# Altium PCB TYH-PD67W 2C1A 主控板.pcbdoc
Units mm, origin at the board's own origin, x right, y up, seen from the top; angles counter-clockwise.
Board outline 94.32 x 66.89 mm, 5 copper layers (Top Layer, Signal Layer 3, Signal Layer 1, Signal Layer 2, Bottom Layer), stack 0.941 mm thick; 54 components, 153 nets, 193 pads, 200 vias.
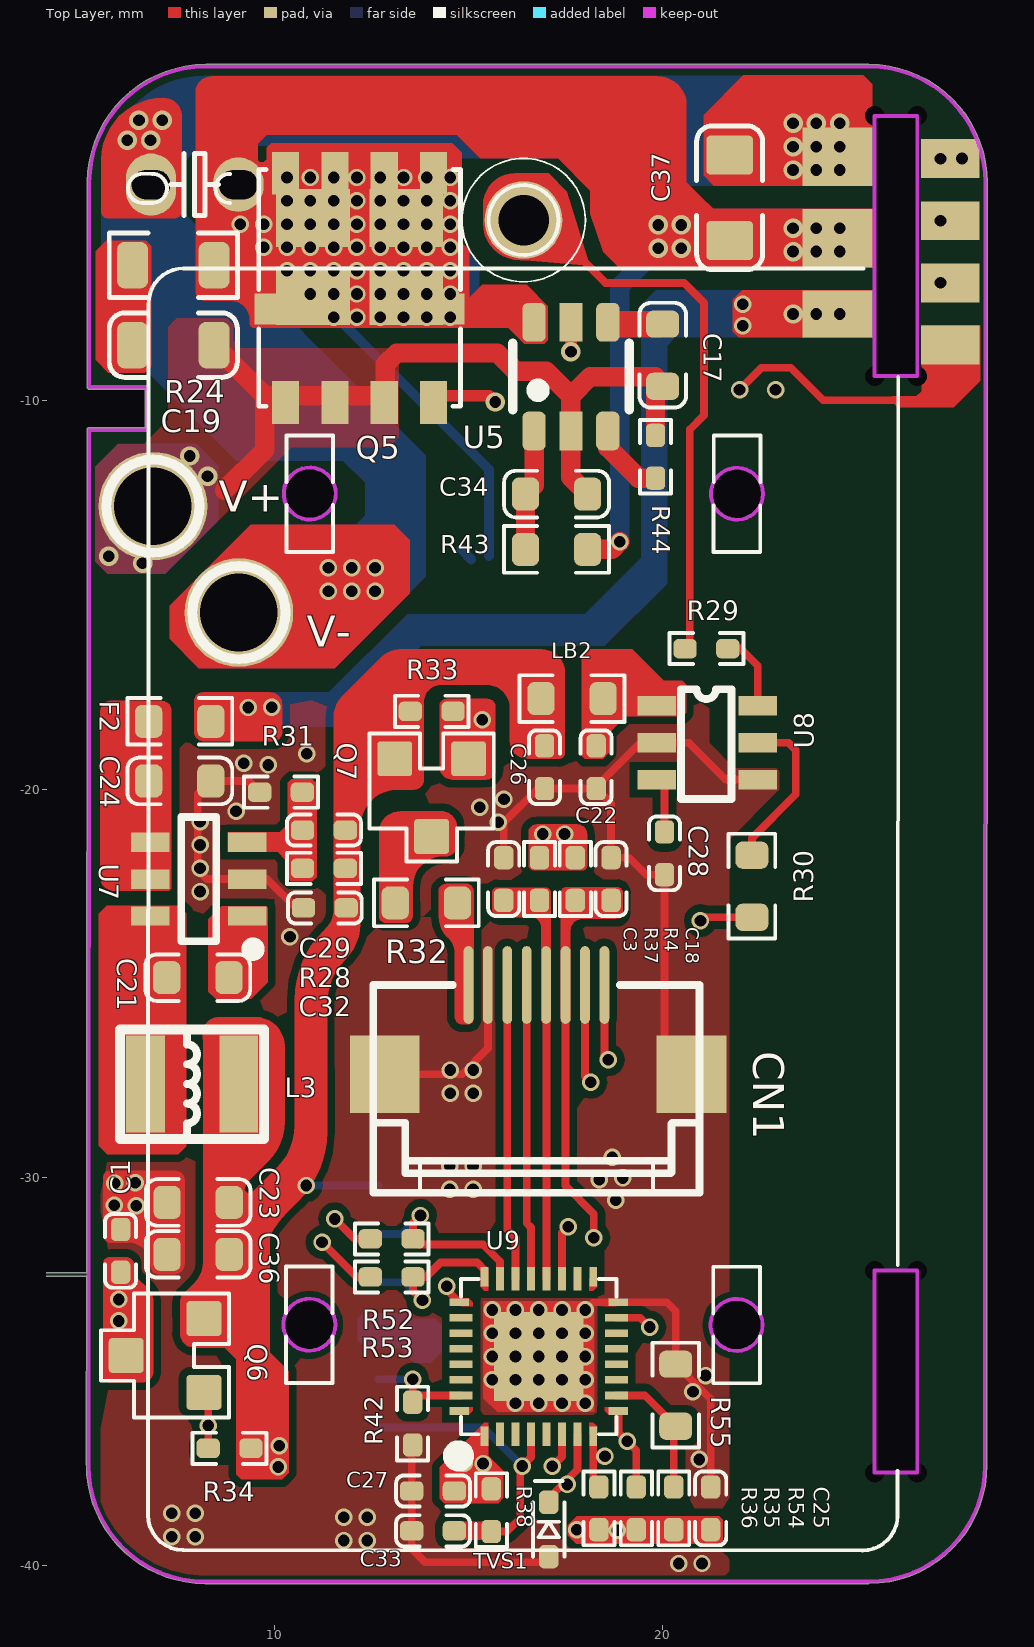
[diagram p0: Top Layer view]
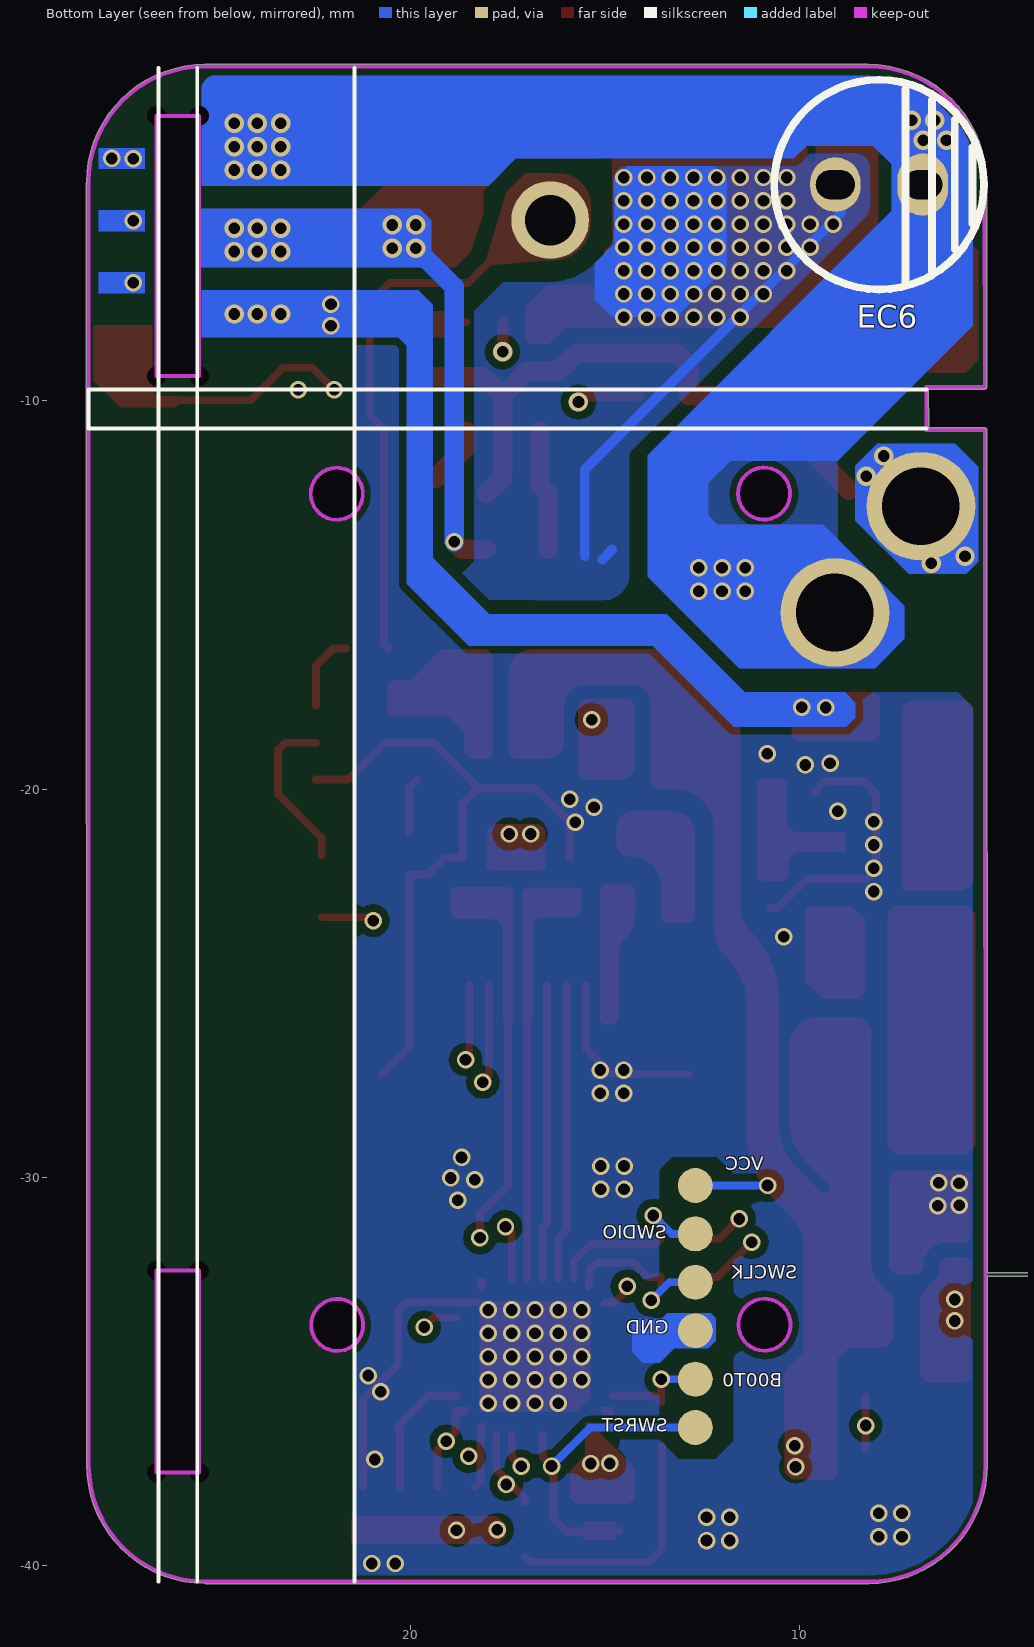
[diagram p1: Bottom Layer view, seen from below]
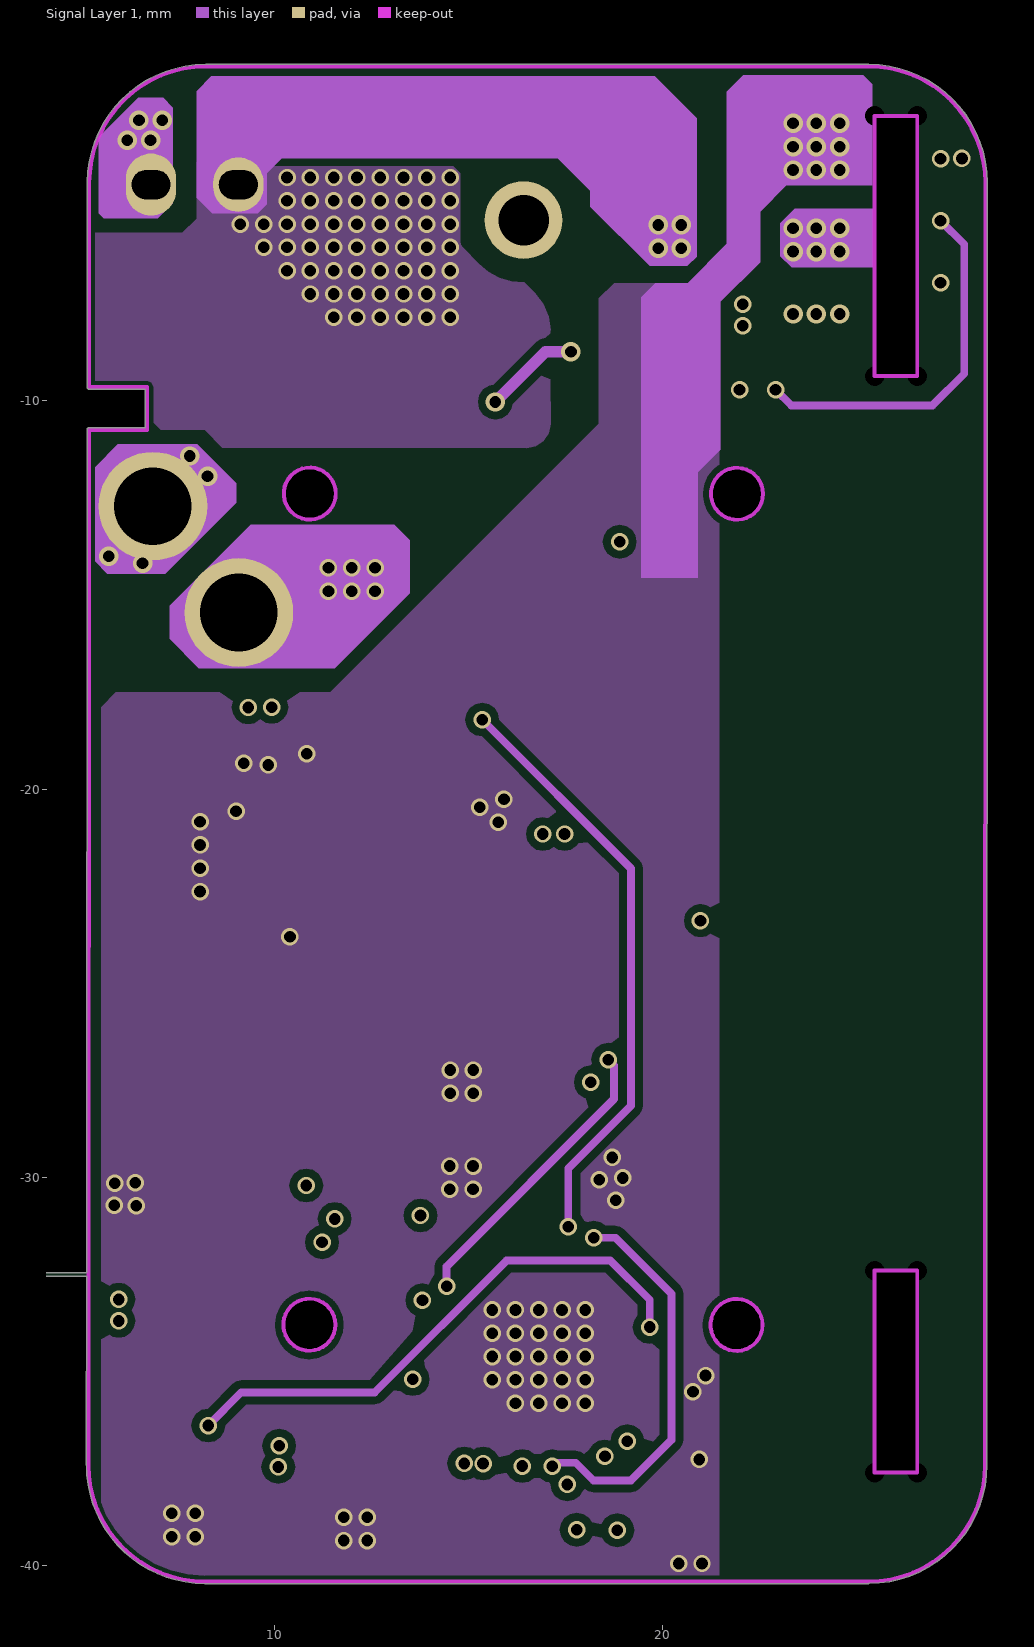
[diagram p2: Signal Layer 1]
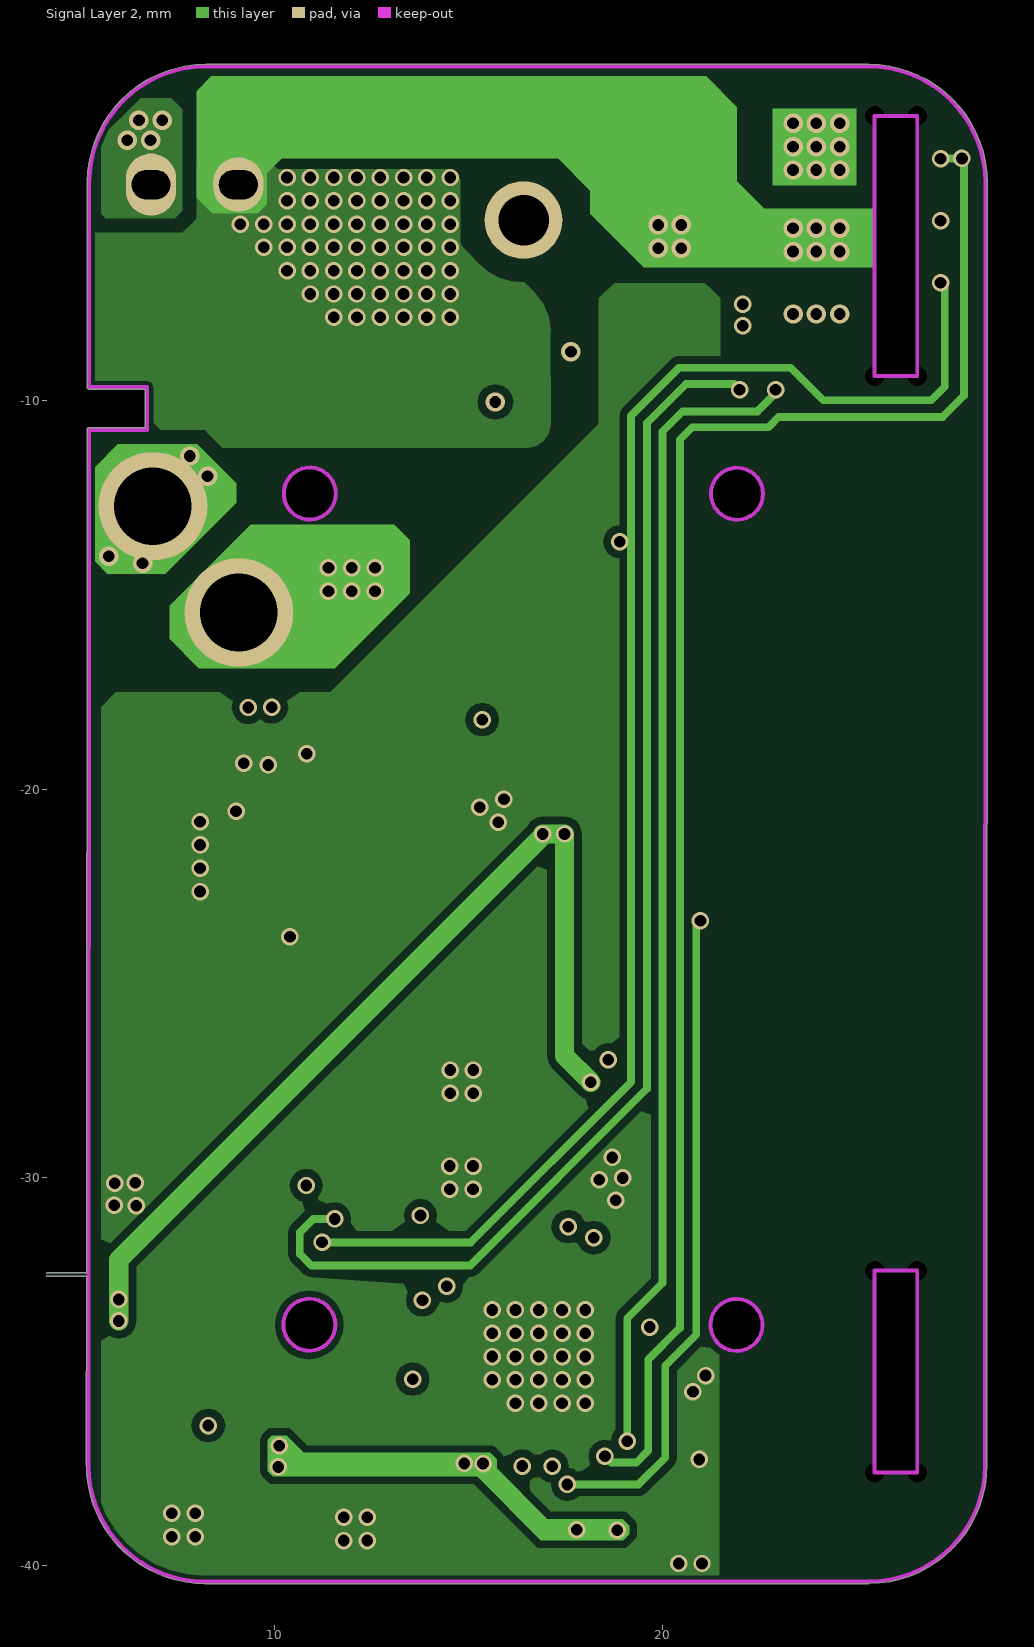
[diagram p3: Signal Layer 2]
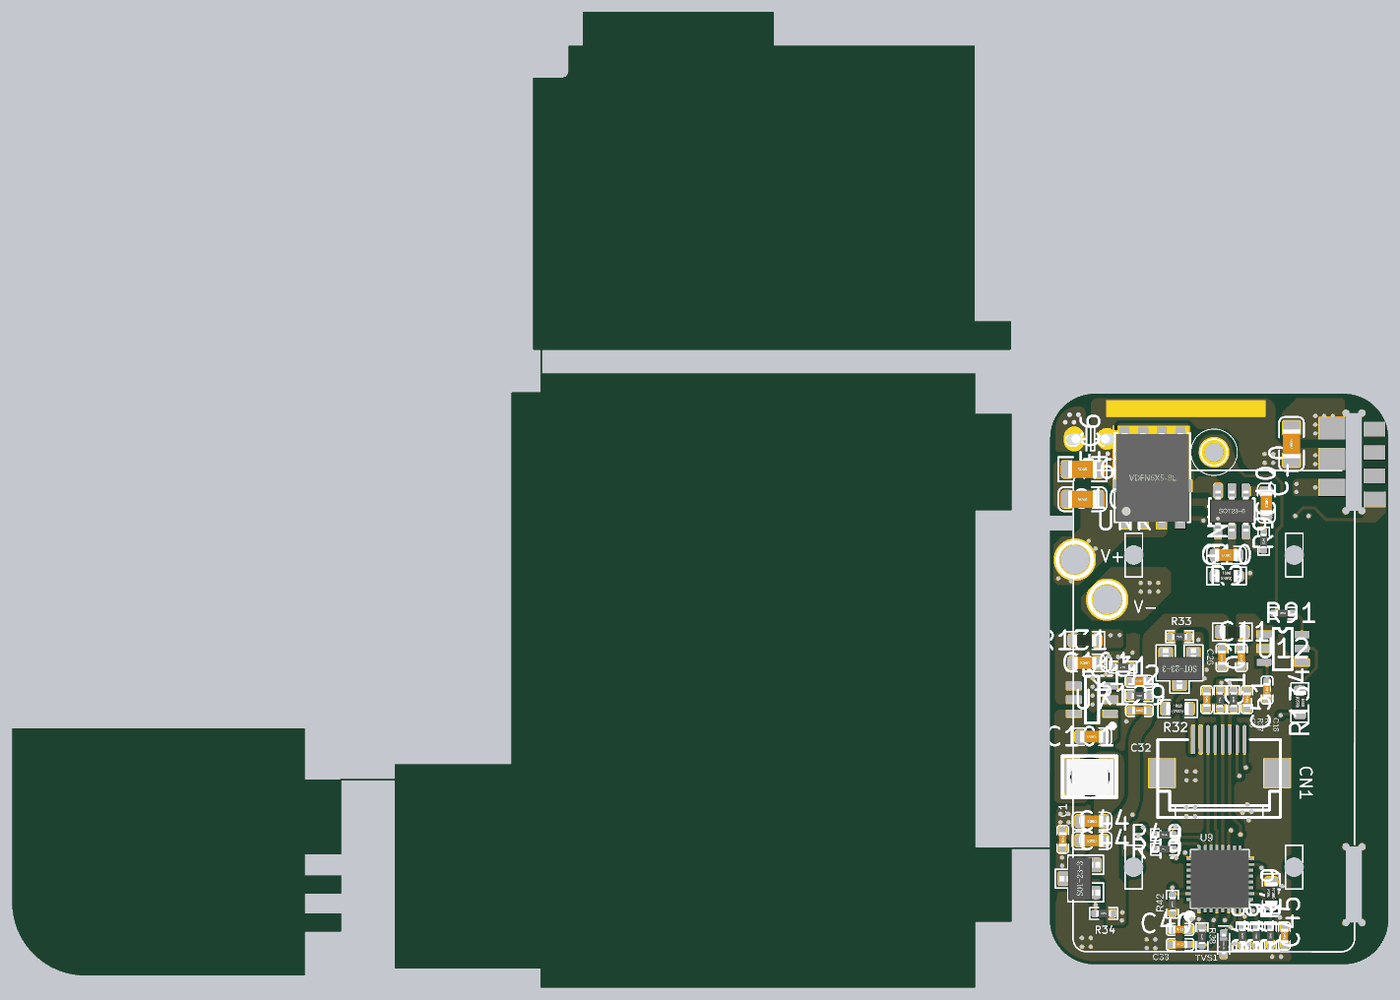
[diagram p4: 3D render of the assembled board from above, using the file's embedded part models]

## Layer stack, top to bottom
Top Solder: solder mask 0.0102, Solder Resist, Dk 3.5
Top Layer: signal copper 0.0356
Dielectric 1: core 0.254, FR-4, Dk 4.2
Signal Layer 3: signal copper 0.036
Dielectric 4: prepreg 0.127, Dk 4.2
Signal Layer 1: signal copper 0.036
Dielectric 2: core 0.254, Dk 4.2
Signal Layer 2: signal copper 0.036
Dielectric 3: prepreg 0.127, Dk 4.2
Bottom Layer: signal copper 0.0356
Bottom Solder: solder mask 0.0102, Solder Resist, Dk 3.5

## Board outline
-60.945,-41.225 -45.944,-41.225 ccw(c-45.944,-41.2) -45.919,-41.2 -45.919,-38.225 -43.445,-38.225 ccw(c-43.445,-38.2) -43.419,-38.2 -43.419,-37 ccw(c-43.445,-37) -43.445,-36.975 -45.919,-36.975 -45.919,-35.625 -43.445,-35.625 ccw(c-43.445,-35.6) -43.419,-35.6 -43.419,-34.4 ccw(c-43.445,-34.4) -43.445,-34.375 -45.919,-34.375 -45.919,-32.925 -43.445,-32.925 ccw(c-43.445,-32.9) -43.419,-32.9 -43.419,-27.85 -39.751,-27.85 -39.759,-40.693 ccw(c-39.709,-40.7) -39.709,-40.75 -29.759,-40.752 -29.76,-42.002 ccw(c-29.71,-42.002) -29.71,-42.052 0,-42.052 ccw(c0,-42.002) 0.05,-42.002 0.05,-37.55 2.5,-37.55 ccw(c2.5,-37.5) 2.55,-37.5 2.55,-32.55 5.163,-32.55 5.16,-37.409 ccw(c5.21,-37.409) 5.16,-37.409 ccw(c8.207,-37.409) 8.207,-40.456 ccw(c8.207,-40.406) 8.207,-40.456 ccw(c8.207,-40.406) 8.207,-40.456 25.296,-40.456 ccw(c25.296,-40.406) 25.308,-40.455 ccw(c25.296,-37.407) 28.344,-37.407 28.352,-4.393 ccw(c28.302,-4.393) 28.352,-4.393 ccw(c28.302,-4.393) 28.351,-4.381 ccw(c25.304,-4.393) 25.304,-1.346 8.229,-1.346 ccw(c8.229,-4.393) 5.181,-4.375 ccw(c5.228,-4.393) 5.178,-4.393 5.175,-9.653 ccw(c5.225,-9.653) 5.225,-9.703 6.674,-9.704 6.673,-10.703 5.225,-10.702 ccw(c5.225,-10.753) 5.174,-10.753 5.163,-32.45 0.05,-32.45 0.05,-9.32 2.5,-9.32 ccw(c2.5,-9.269) 2.55,-9.269 2.55,-2.769 ccw(c2.5,-2.769) 2.5,-2.719 0.05,-2.719 0.05,0 ccw(c0,0) 0,0.05 -29.65,0.05 -29.65,1.682 2.433,1.682 ccw(c2.433,1.733) 2.483,1.733 ccw(c2.433,1.733) 2.482,1.745 ccw(c2.45,1.784) 2.5,1.784 2.5,3.584 ccw(c2.45,3.584) 2.45,3.635 0,3.635 0,22.484 ccw(c-0.05,22.484) -0.014,22.52 ccw(c-0.05,22.484) -0.05,22.535 -13.768,22.535 -13.768,24.784 ccw(c-13.819,24.784) -13.819,24.835 -26.819,24.835 ccw(c-26.819,24.784) -26.869,24.784 -26.869,22.535 -27.789,22.535 ccw(c-27.789,22.484) -27.84,22.483 -27.84,20.784 cw(c-28.289,20.784) -28.289,20.335 cw(c-28.289,20.784) -28.289,20.335 cw(c-28.289,20.284) -28.289,20.335 -30.217,20.335 ccw(c-30.217,20.284) -30.268,20.284 -30.268,1.733 ccw(c-30.217,1.733) -30.217,1.682 -29.75,1.682 -29.75,-1.25 -31.7,-1.25 ccw(c-31.7,-1.3) -31.75,-1.3 -31.75,-26.75 -39.7,-26.75 ccw(c-39.7,-26.8) -39.75,-26.8 -39.751,-27.75 -43.445,-27.75 ccw(c-43.445,-27.8) -43.488,-27.775 -45.919,-27.775 -45.919,-24.3 ccw(c-45.945,-24.3) -45.945,-24.275 -65.945,-24.275 ccw(c-65.945,-24.3) -65.97,-24.3 -65.97,-36.2 ccw(c-60.945,-36.2)
cut-out: 26.55,-32.4 25.45,-32.4 25.45,-37.6 26.55,-37.6
cut-out: 25.45,-9.369 26.55,-9.369 26.55,-2.669 25.45,-2.669
cut-out: 11.579,-12.393 11.579,-12.392 ccw(c10.912,-12.392) 10.912,-11.725 10.902,-11.725 ccw(c10.902,-12.39) 10.237,-12.39 10.237,-12.418 ccw(c10.889,-12.418) 10.889,-13.07 10.902,-13.07 ccw(c10.902,-12.393)
cut-out: 11.567,-33.793 11.567,-33.792 ccw(c10.9,-33.792) 10.9,-33.125 10.89,-33.125 ccw(c10.89,-33.79) 10.226,-33.79 10.226,-33.818 ccw(c10.877,-33.818) 10.877,-34.47 10.89,-34.47 ccw(c10.89,-33.793)
cut-out: 22.567,-33.799 22.567,-33.798 ccw(c21.9,-33.798) 21.9,-33.131 21.89,-33.131 ccw(c21.89,-33.796) 21.226,-33.796 21.226,-33.824 ccw(c21.877,-33.824) 21.877,-34.476 21.89,-34.476 ccw(c21.89,-33.799)
cut-out: 22.579,-12.399 22.579,-12.398 ccw(c21.912,-12.398) 21.912,-11.731 21.902,-11.731 ccw(c21.902,-12.396) 21.237,-12.396 21.237,-12.424 ccw(c21.889,-12.424) 21.889,-13.076 21.902,-13.076 ccw(c21.902,-12.399)

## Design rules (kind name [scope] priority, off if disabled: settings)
Clearance Clearance_19 [InNet('NetC4_2') vs InNet('PGND')] p1: gap=0.4
Clearance Clearance_18 [InNet('NetR15_1') vs InNet('PGND')] p2: gap=1
Clearance Clearance_17 [InNet('NetN_1') vs InNet('NetBD1_1')] p3: gap=1.55
Clearance Clearance_16 [InNet('NetN_1') vs InNet('PGND')] p4: gap=1.5
Clearance Clearance_15 [InNet('VIN') vs InNet('PGND')] p5 off: gap=5.8
Clearance Clearance_14 [InNet('CS') vs InNet('Bais-L')] p6: gap=0.45
Clearance Clearance_13 [InNet('SW') vs InNet('CS')] p7: gap=1.5
Clearance Clearance_12 [InNet('NetR15_1') vs InNet('CS')] p8: gap=1
Clearance Clearance_11 [InNet('NetBD1_3') vs InNet('CS')] p9: gap=1.1
Clearance Clearance_10 [InNet('HV') vs InNet('CS')] p10: gap=1.1
Clearance Clearance_9 [InNet('NetL2_1') vs InNet('CS')] p11: gap=1.5
Clearance Clearance_8 [InNet('NetC1_2') vs InNet('PGND')] p12: gap=1.2
Clearance Clearance_7 [InNet('NetBD1_3') vs InNet('PGND')] p13: gap=1.2
Clearance Clearance_6 [InNet('NetC2_2') vs InNet('PGND')] p14: gap=1.3
Clearance Clearance_5 [InNet('Bais-L') vs InNet('PGND')] p15: gap=0.45
Clearance Clearance_4 [InNet('SW') vs InNet('PGND')] p16: gap=1.5
Clearance Clearance_3 [InNet('HV') vs InNet('PGND')] p17: gap=1.2
Clearance Clearance_2 [InNet('NetL2_1') vs InNet('PGND')] p18: gap=1.5
Clearance Clearance_1 [OnLayer('Keep-Out Layer')] p19: gap=0.1
Clearance [All] p20: gap=0.2
PlaneConnect [All] p1: planeconnectstyle=Direct reliefexpansion=0.508 reliefentries=4 reliefconductorwidth=0.3 reliefairgap=0.254
PolygonConnect [All] p1: connectstyle=Direct reliefconductorwidth=0.3 reliefentries=4 polygonreliefangle="90 Angle" airgapwidth=0.3
RoutingVias [All] p1: holewidth=0.711 width=1.27 viastyle="Through Hole" minholewidth=0.711 minwidth=1.27 maxholewidth=0.711 maxwidth=1.27
SolderMaskExpansion [All] p1: expansion=0.05
Width [All] p1: maxlimit=10 minlimit=0.1 preferedwidth=0.2
28 further rules are at their usual default settings.

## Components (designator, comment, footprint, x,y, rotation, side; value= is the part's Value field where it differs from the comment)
C1 "100nF 0402" 0402C 6.439,-30.942 r270 top
C3 "NC/0402" 0402C 16.302,-21.368 r270 top
C17 "2.2nF/250V/0805" 0603CX#1 19.995,-8.031 r270 top (schematic designator C10)
C18 "NC/0402" 0402C 19.066,-21.368 r270 top (schematic designator C2)
C19 "2.2nF/250V/0805" 0805CX 8.445,-8.572 r180 top (schematic designator C10)
C21 "104/50V X7R 0603" 0603CX#1 7.226,-24.856 r0 top (schematic designator C101)
C22 "106/10V" 0402C 17.882,-20.389 r90 top (schematic designator C101)
C23 "10uF/10V" 0603CX#1 8.836,-30.645 r180 top (schematic designator C44)
C24 "104/50V X7R 0603" 0603CX#1 8.361,-19.794 r180 top (schematic designator C101)
C25 "1uF/25V" 0402C 21.631,-37.57 r270 top (schematic designator C45)
C26 "10nF" 0402C 16.553,-20.389 r90 top (schematic designator C4)
C27 "0.1uF/25V" 0402C 13.132,-37.674 r0 top (schematic designator C40)
C28 "104/25V/NC" 0402C 19.642,-22.606 r90 top (schematic designator C51)
C29 "NC" 0402C 10.323,-20.658 r0 top (schematic designator C112)
C32 "1uF" 0402C 10.347,-22.661 r0 top (schematic designator C5)
C33 "100nF" 0402C 13.132,-38.7 r0 top (schematic designator C6)
C34 "2.2nF/250V/0805" 0603CX#2 17.262,-12.406 r180 top (schematic designator C10)
C36 "10uF/10V" 0603CX#1 8.836,-31.982 r180 top (schematic designator C44)
C37 "2.2nF/250V/0805" 0805C 20.869,-6.628 r90 top (schematic designator C10)
CN1 "8.07A0.006200" "70W 屏座" 16.693,-25.17 r270 top locked
EC6 "560uF/25V/6.3*16" EG-5*17L 7.946,-4.438 r90 bottom
F2 "10KF 0402" 0603LX 6.761,-18.259 r0 top (schematic designator R131)
L3 "3.3uH NR3010" NR3010 7.885,-27.593 r0 top (schematic designator L4)
LB2 "104/25V" 0603LX 18.462,-17.671 r180 top (schematic designator C11)
Q5 "Comment" DFN5*6 10.286,-10.048 r0 top
Q6 "2N7002KL SOT-23" SOT-23_R 7.183,-34.585 r90 top (schematic designator Q8)
Q7 "2N7002KL SOT-23" SOT-23_R 14.047,-20.221 r180 top (schematic designator Q8)
R4 "4.7K" 0402R 17.745,-21.768 r270 top
R24 "10R/1206" 0805RX 8.445,-6.513 r180 top (schematic designator R6)
R28 "31.6KF 0402" 0402R 10.723,-22.042 r0 top (schematic designator R129)
R29 "10K" 0402R 21.672,-16.386 r180 top (schematic designator R91)
R30 "100R" 0603RX#1 22.293,-22.503 r270 top (schematic designator R134)
R31 "10KF 0402" 0402R 9.618,-20.082 r0 top (schematic designator R131)
R32 "10R" 0603RX#2 13.11,-22.934 r0 top (schematic designator R2)
R33 "10K" 0402R 13.498,-18 r0 top (schematic designator R1)
R34 "10K" 0402R 9.393,-36.975 r180 top (schematic designator R3)
R35 "4K7 NC" 0402R 19.316,-37.97 r270 top (schematic designator R49)
R36 "4K7 NC" 0402R 18.353,-37.97 r270 top (schematic designator R49)
R37 "4.7K" 0402R 16.823,-21.768 r270 top (schematic designator R5)
R38 "10K" 0402R 15.583,-39.117 r90 top (schematic designator R6)
R42 "10K" 0402R 13.558,-36.889 r90 top (schematic designator R7)
R43 "51R/0402" 0603RX#1 17.263,-13.831 r0 top (schematic designator R9)
R44 "51R/0402" 0402R 19.81,-10.896 r270 top (schematic designator R9)
R52 "4K7 NC" 0402R 12.468,-31.582 r0 top (schematic designator R49)
R53 "4K7 NC" 0402R 12.468,-32.563 r0 top (schematic designator R49)
R54 "4K7 NC" 0402R 20.28,-37.97 r270 top (schematic designator R49)
R55 "4K7 NC" 0603rx 20.33,-35.608 r90 top (schematic designator R49)
TVS1 "Comment" SOD-723 17.062,-39.065 r90 top
U5 "Comment" SOT-23-6S 16.683,-10.783 r90 top
U7 "RY9420BT6" SOT-23-6#1 8.051,-22.32 r180 top
U8 "RM1233A" SOT-23-6#2 21.143,-18.808 r0 top (schematic designator U12)
U9 "Comment" "QFN4*4-32L TYH" 16.805,-34.612 r0 top
V+ "Comment" PAD-AC 6.869,-12.718 r0 top
V- "Comment" PAD-AC 9.083,-15.458 r0 top

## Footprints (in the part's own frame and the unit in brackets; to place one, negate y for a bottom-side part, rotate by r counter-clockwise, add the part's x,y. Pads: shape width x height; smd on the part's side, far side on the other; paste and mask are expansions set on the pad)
"70W 屏座" [mm]
  oval 2x0.25 smd: 1(-0.124,-1.698) 2(-0.124,-1.198) 3(-0.124,-0.698) 4(-0.124,-0.198) 5(-0.124,0.302) 6(-0.124,0.802) 7(-0.124,1.302) 8(-0.124,1.802)
  rect 2x1.8 smd: 2(2.176,-3.855) 2(2.176,4.045)
  silkscreen extent -0.12,-4.15 5.23,4.25
0402C [mm]
  rrect50% 0.6x0.5 smd: 1(0.4,-0.4) 2(1.5,-0.4)
  silkscreen extent 0,-0.8 1.9,0, body extent 0.45,-0.66 1.45,-0.14, height 0.53
0402R [mm]
  rrect50% 0.6x0.5 smd: 1(0,0) 2(1.1,0)
  silkscreen extent -0.4,-0.4 1.5,0.4, body extent 0.05,-0.25 1.05,0.25, height 0.3
0603CX#1 [mm]
  rrect50% 0.7x0.85 smd: 1(0,0) 2(1.6,0)
  silkscreen extent -0.55,-0.6 2.15,0.6, body extent 0,-0.41 1.6,0.41, height 0.81
0603CX#2 [mm]
  rrect50% 0.7x0.85 smd: 1(-0.8,0) 2(0.8,0)
  silkscreen extent -1.35,-0.6 1.35,0.6, body extent -0.8,-0.41 0.8,0.41, height 0.81
0603LX [mm]
  rrect50% 0.7x0.85 smd: 1(0,0) 2(1.6,0)
  silkscreen extent -0.55,-0.6 2.15,0.6, body extent -0.02,-0.4 1.58,0.4, height 0.4
0603RX#1 [mm]
  rrect50% 0.7x0.85 smd: 1(-0.8,0) 2(0.8,0)
  silkscreen extent -1.35,-0.6 1.35,0.6, body extent -0.77,-0.42 0.78,0.43, height 0.45
0603RX#2 [mm]
  rrect50% 0.7x0.85 smd: 1(0,0) 2(1.6,0)
  silkscreen extent -0.55,-0.6 2.15,0.6, body extent 0.03,-0.42 1.58,0.43, height 0.45
0603rx [mm]
  rrect50% 0.7x0.85 smd: 1(-0.8,0) 2(0.8,0)
  silkscreen extent -1.35,-0.6 1.35,0.6, body extent -0.77,-0.42 0.78,0.43, height 0.45
0805C [mm]
  rrect20% 1x1.2 smd: 1(0.75,-0.85) 2(2.95,-0.85)
  silkscreen extent 0,-1.7 3.7,0, body extent 0.85,-1.46 2.85,-0.24, height 0.51
0805CX [mm]
  rrect50% 0.8x1.2 smd: 1(0,0) 2(2.1,0)
  silkscreen extent -0.6,-0.83 2.7,0.83, body extent 0.05,-0.61 2.05,0.61, height 0.51
0805RX [mm]
  rrect50% 0.8x1.2 smd: 1(0,0) 2(2.1,0)
  silkscreen extent -0.6,-0.83 2.7,0.83, body extent 0.05,-0.61 2.05,0.61, height 0.51
DFN5*6 [mm]
  rect 0.7x1.1 smd: 1(0,0) 2(1.27,0) 3(2.54,0) 4(3.81,0) 5(3.81,5.9) 6(2.54,5.9) 7(1.27,5.9) 8(0,5.9)
  rect 1x0.8 smd: 8(-0.295,2.402) 8(4.105,2.402)
  rect 1.9x1.5 smd: 8(0.705,2.75) 8(0.705,4.75) 8(3.105,2.75) 8(3.105,4.75)
  silkscreen extent -0.69,-0.1 4.51,6, body extent -0.59,-0.1 4.41,6, height 1.06
EG-5*17L [mm]
  oval 1.4x1.3 hole 0.75 slot 1 at 90 deg: 1(0,1.125)
  oval 1.6x1.3 hole 0.75 slot 1 at 90 deg: 2(0,-1.125)
  silkscreen extent -2.7,-2.7 2.7,2.7, body extent -2.7,-2.7 2.7,2.7, height 17
NR3010 [mm]
  rect 1x2.5 smd: 1(-1.206,-0.001) 2(1.194,-0.001)
  silkscreen extent -1.87,-1.42 1.84,1.4, body extent -1.58,-1.38 1.63,1.34, height 2
PAD-AC [mm]
  round 2.8 hole 2: 1(0,0)
  silkscreen extent -1.2,-1.2 1.2,1.2
"QFN4*4-32L TYH" [mm]
  rect 0.2x0.5 smd: 1(-1.4,-2.05) 8(1.4,-2.05) 17(1.4,2.05) 24(-1.4,2.05)
  rect 0.2x0.6 smd: 2(-1,-2) 3(-0.6,-2) 4(-0.2,-2) 5(0.2,-2) 6(0.6,-2) 7(1,-2) 18(1,2) 19(0.6,2) 20(0.2,2) 21(-0.2,2) 22(-0.6,2) 23(-1,2)
  rect 0.5x0.2 smd: 9(2.05,-1.4) 16(2.05,1.4) 25(-2.05,1.4) 32(-2.05,-1.4)
  rect 0.6x0.2 smd: 10(2,-1) 11(2,-0.6) 12(2,-0.2) 13(2,0.2) 14(2,0.6) 15(2,1) 26(-2,1) 27(-2,0.6) 28(-2,0.2) 29(-2,-0.2) 30(-2,-0.6) 31(-2,-1)
  rect 2.3x2.3 smd: 33(0,0)
  Top Layer region: -1.425,1.425 1.425,1.425 1.425,-1.425 -1.075,-1.425 -1.425,-1.075
  Top Layer region: -2,-1.5 -1.8,-1.5 -1.7,-1.4 -1.7,-1.3 -2,-1.3
  Top Layer region: -2,1.5 -1.8,1.5 -1.7,1.4 -1.7,1.3 -2,1.3
  Top Layer region: 1.5,-2 1.5,-1.8 1.4,-1.7 1.3,-1.7 1.3,-2
  Top Layer region: -1.5,-2 -1.5,-1.8 -1.4,-1.7 -1.3,-1.7 -1.3,-2
  Top Layer region: 2,-1.5 1.8,-1.5 1.7,-1.4 1.7,-1.3 2,-1.3
  Top Layer region: 2,1.5 1.8,1.5 1.7,1.4 1.7,1.3 2,1.3
  Top Layer region: 1.5,2 1.5,1.8 1.4,1.7 1.3,1.7 1.3,2
  Top Layer region: -1.5,2 -1.5,1.8 -1.4,1.7 -1.3,1.7 -1.3,2
  silkscreen extent -2.27,-2.76 2,2, body extent -2,-2 2,2, height 0.75
SOD-723 [mm]
  rrect50% 0.6x0.5 smd: 1(-0.7,0) 2(0.7,0)
  silkscreen extent -0.7,-0.41 1.25,0.41, body extent -0.7,-0.3 0.7,0.3, height 0.53
SOT-23-6#1 [mm]
  rect 1x0.5 smd: 1(-1.25,0.95) 2(-1.25,0) 3(-1.25,-0.95) 4(1.25,-0.95) 5(1.25,0) 6(1.25,0.95)
  silkscreen extent -1.5,-1.6 0.45,1.9, body extent -1.4,-1.5 1.4,1.5, height 1.15
SOT-23-6#2 [mm]
  rect 1x0.5 smd: 1(-1.3,0.95) 2(-1.3,0) 3(-1.3,-0.95) 4(1.3,-0.95) 5(1.3,0) 6(1.3,0.95)
  silkscreen extent -0.67,-1.45 0.63,1.37
SOT-23-6S [mm]
  rrect50% 1x0.6 smd: 1(0,0) 3(0,-1.9) 4(2.8,-1.9) 6(2.8,0)
  rect 1x0.6 smd: 2(0,-0.95) 5(2.8,-0.95)
  silkscreen extent 0.55,-2.45 2.25,0.55, body extent -0.01,-2.45 2.8,0.55, height 1.15
SOT-23_R [mm]
  rrect20% 0.9x0.9 smd: 1(-0.95,-1) 2(0.95,-1) 3(0,1)
  silkscreen extent -1.6,-1.65 1.6,1.65, body extent -1.46,-1.44 1.44,1.36, height 1.2

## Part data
C1 C3 C18 C26 C32 C33: library part CAP_0603
C17 C19 C34 C37: library part CAP
C23 C25 C27 C36: library part CAP, "X7R, 25V, +/-5%"
C29: library part "CAP SEMI"
EC6: library part CAPACITOR, "C?"
L3: library part Inductor, "102125 铁?"
LB2: library part CAPZ
Q6 Q7: library part NMOS
R4 R32 R33 R34 R37 R38 R42: library part Res_0603
R24 R43 R44: library part Res1, "Resistor"
R35 R36 R52 R53 R54 R55: library part RES2Z
U7: library part ME3121, "DC-DC BUCK"
U8: "U?"

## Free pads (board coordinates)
  round 0.9 smd far side: 0(12.678,-36.441) 0(12.678,-35.195) 0(12.678,-33.948) 0(12.678,-32.702) 0(12.678,-31.455) 0(12.678,-30.209)
  round 2 hole 1.3: 0(16.412,-5.352)
  rect 1.8x1.2 smd: 3(24.5,-7.769)
  rect 1.8x1.5 smd: 3(24.5,-5.819) 3(24.5,-3.719)
  rect 1.5x1 smd: 3(27.4,-8.569) 3(27.4,-6.969) 3(27.4,-5.369) 3(27.4,-3.769)
  round 0.2 hole 0.5: 8(26.55,-9.369) 9(25.45,-9.369) 10(25.45,-2.669) 11(26.55,-2.669) 12(25.45,-32.4) 13(26.55,-32.4) 14(25.45,-37.6) 15(26.55,-37.6)

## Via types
v1: diameter 0.45, hole 0.3, Top Layer to Bottom Layer, tented both sides, 168 vias
v2: diameter 0.5, hole 0.3, Top Layer to Bottom Layer, tented both sides, 32 vias

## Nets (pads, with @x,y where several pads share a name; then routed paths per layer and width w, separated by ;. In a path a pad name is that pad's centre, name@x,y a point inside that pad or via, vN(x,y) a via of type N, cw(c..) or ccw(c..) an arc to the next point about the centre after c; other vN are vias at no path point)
3.3V: C22.2 LB2.1 U8.1 | length 2.8
  Top Layer w0.2: C22.2 18.282,-17.851 LB2.1 18.65,-17.858 U8.1
A: 
A+: 
A-: 
Bais-L: 
BOOT0: pad.0@12.678,-35.195 R42.2 U9.31 | length 2.8
  Top Layer w0.2: v1(13.558,-35.195) R42.2 13.734,-35.612 U9.31
  Bottom Layer w0.2: pad.0@12.678,-35.195 v1(13.558,-35.195)
CC1: 
CC2: 
CPA: 
CS: CN1.8 U9.25 | length 10.3
  Top Layer w0.2: v1(14.432,-32.803) 14.432,-32.89 U9.25 ; CN1.8 18.495,-26.871 v1(18.592,-26.969)
  Signal Layer 1 w0.2: v1@14.534,-32.803 v1(14.432,-32.803) 14.432,-32.293 18.743,-27.983 18.743,-27.119 v1(18.592,-26.969)
D: 
D+: 
D-: 
DM: 
DP: 
EM: 
EN: 
EN_IC: 
FB: 
G-SR: Q5.4 U5.5 | length 4.9
  Top Layer w0.3: Q5.4@14.119,-9.878 15.529,-9.878 v2(15.686,-10.035) ; v2(17.633,-8.744) U5.5
  Signal Layer 1 w0.3: v2(15.686,-10.035) 16.977,-8.744 v2(17.633,-8.744)
GND-C: 
HV: 
ISET: 
KEY: R30.2 TVS1.2 U9.7 | length 20.4
  Top Layer w0.2: TVS1.2 17.062,-38.258 17.805,-37.516 U9.7 ; v1(20.969,-23.388) 21.053,-23.303 R30.2
  Signal Layer 2 w0.2: v1(17.542,-37.905) 19.374,-37.905 20.06,-37.219 20.06,-34.848 20.859,-34.048 20.859,-23.497 v1(20.969,-23.388)
KEY1: R29.1 U8.6 | length 2
  Top Layer w0.2: R29.1 22.004,-16.386 22.443,-16.825 U8.6
LEDA: CN1.1 R32.2
M: 
N: 
NetBD1_1: 
NetBD1_3: 
NetBD2_1: 
NetC1_2: 
NetC2_2: 
NetC3_2: 
NetC4_1: 
NetC4_2: 
NetC6_1: 
NetC10_2: C19.2 R24.2 | length 2.1
  Top Layer w0.254: C19.2@6.306,-8.553 R24.2@6.306,-6.494
NetC21_1: 
NetC22_1: 
NetC24_1: C24.2 F2.1 U7.4 U7.5
NetC25_2: 
NetC26_2: 
NetC30_2: 
NetC31_2: 
NetC100_2: 
NetC101_1: C21.1 L3.1 U7.6
NetC101_2: C21.2 U7.1
NetC112_1: C29.1 R28.1 R31.2 U7.3
NetD4_K: 
NetF1_1: 
NetF1_2: 
NetKEY1_1: pad.0@16.412,-5.352 R29.2 | length 14.6
  Top Layer w0.2: pad.0@16.412,-5.352 16.906,-5.352 18.523,-6.97 20.545,-6.97 21.058,-7.484 21.058,-10.379 20.691,-10.746 20.691,-16.267 R29.2
NetL2_1: 
NetLF1_2: 
NetN_1: 
NetNTC2_1: 
NetQ1_3: Q7.3 R32.1
NetQ3_4: 
NetR15_1: 
NetR25_2: 
NetR29_1: 
NetR31_2: 
NetR32_2: 
NetR41_2: 
NetR42_2: 
NetR134_1: R30.1 U8.5 | length 4.2
  Top Layer w0.2: R30.1 22.293,-21.265 23.422,-20.137 23.422,-18.994 23.236,-18.808 U8.5
NetRX1_2: 
NetRX3_2: 
NetU1_26: U9.26
NetU1_27: U9.27
NetU1_28: U9.28
NetU1_29: U9.29
NetU1_30: U9.30
NetU1_32: U9.32
NewNet1: 
NewNet2: 
NewNet3: 
NewNet4: 
NewNet5: 
NewNet6: 
NewNet7: 
NewNet8: 
NewNet9: 
NewNet10: 
NewNet11: 
NewNet12: 
NewNet13: 
NewNet14: 
NewNet15: 
NewNet16: 
NewNet18: 
NewNet22: 
NewNet23: 
NewNet24: 
NewNet25: 
NewNet28: 
NewNet32: 
NewNet33: 
NewNet34: 
NewNet36: 
NewNet38: 
NewNet40: 
NewNet41: 
NewNet42: 
OPTO: 
OTP: 
PA2: U9.17
PA4: R54.1 R55.1 U9.10 | length 3.4
  Top Layer w0.2: U9.10 19.535,-35.612 R55.1 20.28,-36.458 R54.1
PA5: U9.11
PA6: U9.12
PA7: U9.13
PA8: U9.18
PA9: Q7.1 R33.2 U9.19 | length 16.7
  Top Layer w0.2: U9.19 17.405,-31.428 v1(17.564,-31.268)
  Signal Layer 1 w0.2: v1(15.347,-18.214) 19.179,-22.046 19.179,-28.155 17.564,-29.77 v1(17.564,-31.268)
PB0: U9.14
PB1: Q6.1 R34.2 U9.15 | length 16.5
  Top Layer w0.2: R34.2 Q6.1@8.293,-35.646 ; U9.15 19.419,-33.612 v1(19.66,-33.854)
  Signal Layer 1 w0.2: v1(8.293,-36.388) 9.146,-35.535 12.582,-35.535 15.976,-32.141 18.647,-32.141 19.66,-33.155 v1(19.66,-33.854)
PF0: U9.2
PF1: U9.3
PF3: U9.5
PGND: 
RS: CN1.4 U9.21 | length 7.6
  Top Layer w0.2: CN1.4 16.495,-31.179 16.605,-31.289 U9.21
RST: CN1.3 U9.22 | length 8
  Top Layer w0.2: CN1.3 15.995,-31.349 ; U9.22 16.205,-31.559 ; 15.995,-31.349 16.205,-31.559 ; 15.995,-31.349 16.205,-31.559
SCL: pad.3@27.4,-3.769 R36.1 U9.8 | length 43.8
  Top Layer w0.2: U9.8 18.205,-37.182 ; R36.1 18.205,-37.822 18.205,-37.182 ; v1(18.509,-37.182) 18.205,-37.182
  Signal Layer 2 w0.2: v1(18.509,-37.182) 18.67,-37.343 19.313,-37.343 19.623,-37.033 19.623,-34.69 20.439,-33.874 20.439,-11.006 20.76,-10.684 22.721,-10.684 22.986,-10.42 27.204,-10.42 27.751,-9.873 27.751,-3.816 v1(27.701,-3.765) ; v1(27.15,-3.769) v1@27.701,-3.769
SCL1: C18.2 CN1.6 R4.2 U9.6 | length 17.8
  Top Layer w0.2: v1(17.156,-37.438) 17.405,-37.189 U9.6 ; CN1.6 17.495,-30.215 18.221,-30.941 v1(18.221,-31.556)
  Signal Layer 1 w0.2: v1@17.168,-37.426 17.246,-37.348 17.757,-37.348 18.211,-37.802 19.18,-37.802 20.223,-36.759 20.223,-33 18.779,-31.556 v1(18.221,-31.556)
SDA: pad.3@27.4,-5.369 R35.1 U9.9 | length 41.5
  Top Layer w0.2: U9.9 18.855,-36.561 19.316,-37.023 R35.1
  Signal Layer 1 w0.2: v1(22.901,-9.717) 23.308,-10.123 26.941,-10.123 27.758,-9.306 27.758,-5.978 v1(27.15,-5.369)
  Signal Layer 2 w0.2: v1(19.085,-36.792) 19.085,-33.626 19.988,-32.724 19.988,-10.801 20.511,-10.278 22.435,-10.278 22.901,-9.811 v1(22.901,-9.717)
SDA1: C3.2 CN1.5 R37.2 U9.20 | length 7.6
  Top Layer w0.2: CN1.5 17.005,-25.055 U9.20
SET: R44.2 U5.3 | length 2
  Top Layer w0.5: U5.3 18.583,-11.209 19.37,-11.996 R44.2
SGND: C1.1 C3.1 C18.1 C22.1 C23.2 C24.1 C25.1 C26.1 C27.1 C28.1 C32.1 C33.1 C36.2 C37.2 CN1.2 EC6.2 pad.0@12.678,-33.948 pad.3@24.5,-3.719 R31.1 R42.1 R55.2 TVS1.1 U7.2 U8.2 U8.4 U9.16 U9.33 V-.1 | length 56.8
  Top Layer w0.2: R31.1 9.33,-19.793 C24.1 8.025,-20.13 8.025,-22.081 8.264,-22.32 U7.2 9.807,-22.32 10.547,-23.061 C32.1 ; CN1.2@12.838,-27.346 14.831,-27.346 15.495,-26.682 CN1.2@15.495,-25.046 ; R42.1@13.532,-36.914 C33.1 13.532,-39.564 13.876,-39.908 16.92,-39.908 TVS1.1 ; C3.1 15.902,-20.863 16.776,-19.989 C26.1 C22.1@18.237,-19.989 ; v1(16.805,-34.612) 18.205,-33.212 U9.16 20.095,-33.212 20.331,-33.448 R55.2 21.231,-35.708 C25.1 ; CN1.2@20.738,-27.346 20.042,-26.649 C28.1 19.571,-22.206 19.133,-21.768 C18.1 18.666,-20.374 C22.1 C22.1@18.237,-19.989 ; U8.4 21.62,-19.758 20.67,-18.808 U8.2 19.418,-18.808 C22.1@18.237,-19.989
  Bottom Layer w0.2: 11.742,-10.813 13.025,-12.096 13.025,-14.004
  Bottom Layer w0.254: EC6.2@6.68,-4.446 6.68,-5.751 11.742,-10.813
  other v1: 20.407,-39.941 21.007,-39.941 11.788,-39.351 12.388,-39.351 7.357,-39.252 7.957,-39.252 11.788,-38.751 12.388,-38.751 7.357,-38.652 7.957,-38.652 20.933,-37.262 16.205,-35.812 16.805,-35.812 17.405,-35.812 18.005,-35.812 20.775,-35.521 15.605,-35.212 16.205,-35.212 16.805,-35.212 17.405,-35.212 18.005,-35.212 21.099,-35.102 15.605,-34.612 16.205,-34.612 17.405,-34.612 18.005,-34.612 15.605,-34.012 16.205,-34.012 16.805,-34.012 17.405,-34.012 18.005,-34.012 15.605,-33.412 16.205,-33.412 16.805,-33.412 17.405,-33.412 18.005,-33.412 5.878,-30.721 6.438,-30.73 18.79,-30.585 14.512,-30.307 15.112,-30.307 5.887,-30.147 6.412,-30.138 18.36,-30.065 18.969,-30.015 14.512,-29.707 15.112,-29.707 18.697,-29.487 14.521,-27.836 15.121,-27.836 14.521,-27.236 15.121,-27.236 10.399,-23.806 8.083,-22.64 8.083,-22.04 8.083,-21.44 15.765,-20.853 8.083,-20.84 9.01,-20.577 15.286,-20.47 15.909,-20.265 9.842,-19.381 9.209,-19.335 10.826,-19.092 11.389,-14.907 11.989,-14.907 12.589,-14.907 11.389,-14.307 11.989,-14.307 12.589,-14.307
  other v2: 23.352,-4.062 23.952,-4.062 24.552,-4.062 23.352,-3.462 23.952,-3.462 24.552,-3.462 6.209,-3.295 6.809,-3.295 23.352,-2.862 23.952,-2.862 24.552,-2.862 6.51,-2.778 7.11,-2.778
SRCG_A: 
SW: 
SW-SR: 
SWCLK: pad.0@12.678,-32.702 R53.2 U9.24 | length 4.3
  Top Layer w0.2: v1(13.809,-33.161) 13.568,-32.92 R53.2 13.901,-32.563 14.274,-32.19 15.217,-32.19 15.405,-32.378 U9.24
  Bottom Layer w0.2: pad.0@12.678,-32.702 13.35,-32.702 v1(13.809,-33.161)
SWCLK1: pad.3@27.4,-6.969 R53.1 | length 40.2
  Top Layer w0.2: v1(11.225,-31.674) 12.114,-32.563 R53.1
  Signal Layer 2 w0.2: v1(11.225,-31.674) 15.051,-31.674 19.179,-27.546 19.179,-10.389 20.415,-9.152 23.291,-9.152 24.126,-9.988 26.91,-9.988 27.255,-9.643 27.255,-7.075 v1(27.15,-6.969)
SWCLK2: 
SWDIO: pad.0@12.678,-31.455 R52.2 U9.23 | length 4.9
  Top Layer w0.2: v1(13.759,-30.981) 13.568,-31.171 R52.2 13.716,-31.73 15.371,-31.73 15.805,-32.163 U9.23
  Bottom Layer w0.2: pad.0@12.678,-31.455 13.284,-31.455 v1(13.759,-30.981)
SWDIO1: pad.3@27.4,-8.569 R52.1 | length 40.8
  Top Layer w0.2: v1(11.548,-31.07) 12.06,-31.582 R52.1 ; v1(21.974,-9.717) 22.539,-9.152 23.291,-9.152 24.126,-9.988 26.91,-9.988 27.4,-9.498 pad.3@27.4,-8.569
  Signal Layer 2 w0.2: v1(11.548,-31.07) 11,-31.07 10.652,-31.418 10.652,-31.969 10.95,-32.267 15.04,-32.267 19.589,-27.718 19.589,-10.578 20.593,-9.574 21.832,-9.574 v1(21.974,-9.717)
SWDIO2: 
SWRST: C33.2 pad.0@12.678,-36.441 R38.1 U9.4 | length 8.2
  Top Layer w0.2: C33.2 R38.1@15.566,-39.1 ; R38.1 15.983,-39.117 16.325,-38.775 16.325,-37.485 16.605,-37.206 U9.4
  Bottom Layer w0.2: pad.0@12.678,-36.441 15.388,-36.441 v1(16.379,-37.432)
TXD: 
U2-2: 
V3V3: C23.1 C25.2 C26.2 C27.2 C29.2 C32.2 C36.1 L3.2 LB2.2 pad.0@12.678,-30.209 Q6.2 Q7.2 R28.2 R33.1 R34.1 R35.2 R36.2 R38.2 R54.2 U9.1 | length 13.9
  Top Layer w0.2: 9.279,-33.972 9.393,-34.087 R34.1 ; C27.2 14.689,-38.017 R38.2 15.405,-37.839 U9.1 ; v1(17.78,-39.07) R36.2 R54.2 C25.2
  Signal Layer 2 w0.2: v1(15.37,-37.367) 17.073,-39.07 v1(17.78,-39.07)
  Bottom Layer w0.2: v1(10.818,-30.209) pad.0@12.678,-30.209
  other v1: 18.826,-39.085 10.096,-37.455 14.884,-37.365 10.121,-36.908
VBUS: 
VC: C28.2 U8.3 | length 1.4
  Top Layer w0.2: U8.3 20.042,-19.958 C28.2
VDD: C1.2 CN1.7 Q6.3 R4.1 R37.1 | length 26.9
  Top Layer w0.2: CN1.7 17.995,-27.396 v1(18.146,-27.547)
  Signal Layer 2 w0.5: v1(5.994,-33.697) v1(5.994,-33.142) 5.994,-32.116 16.911,-21.199 v1(16.911,-21.158) v1(17.467,-21.158) 17.467,-26.869 v1(18.146,-27.547)
VDD1: C17.1 U5.4 | length 1.4
  Top Layer w0.2: U5.4 19.946,-7.983 C17.1
VDS: C17.2 C19.1 C34.1 Q5.1 Q5.2 Q5.3 R44.1 U5.2 V+.1 | length 20.6
  Top Layer w0.5: C19.1 9.751,-9.878 ; 8.713,-12.303 9.751,-11.265 9.751,-9.878 ; C34.1 17.633,-11.976 17.633,-11.488 U5.2 17.633,-9.88 ; R44.1 19.81,-9.382 19.809,-9.383 18.13,-9.383 17.633,-9.88 ; 9.751,-9.878 12.849,-9.878 12.849,-9.072 13.148,-8.774 15.736,-8.774 16.203,-9.241 16.994,-9.241 17.633,-9.88
  other v2: 6.604,-14.19 5.734,-14.004 8.277,-11.944 7.822,-11.426
VFB: 
VFB1: 
VIN: C37.1 EC6.1 pad.3@24.5,-5.819 Q5.5 Q5.6 Q5.7 Q5.8 R24.1 R43.2 U5.6 | length 39.6
  Top Layer w0.254: 8.275,-7.144 Q5.8@10.749,-7.144 ; R24.1 8.445,-4.931 EC6.1@8.93,-4.446 ; Q5.6@12.849,-3.978 9.398,-3.978 EC6.1@8.93,-4.446 ; Q5.8@13.414,-7.128 13.414,-5.128 9.613,-5.128 EC6.1@8.93,-4.446 ; Q5.8@14.391,-7.647 16.346,-7.647 U5.6@16.683,-7.983
  Top Layer w0.5: R43.2 18.69,-13.831 v1(18.887,-13.634)
  Bottom Layer w0.254: EC6.1@8.93,-4.446 8.93,-5.175 15.525,-11.77 15.525,-14.004 ; 14.817,-13.836 15.067,-14.087
  Bottom Layer w0.5: v1(18.887,-13.634) 18.887,-7.067 v2(19.877,-6.077)
  other v1: 11.523,-7.855 12.123,-7.855 12.723,-7.855 13.323,-7.855 13.923,-7.855 14.523,-7.855 10.923,-7.255 11.523,-7.255 12.123,-7.255 12.723,-7.255 13.323,-7.255 13.923,-7.255 14.523,-7.255 10.323,-6.655 10.923,-6.655 11.523,-6.655 12.123,-6.655 12.723,-6.655 13.323,-6.655 13.923,-6.655 14.523,-6.655 9.723,-6.055 10.323,-6.055 10.923,-6.055 11.523,-6.055 12.123,-6.055 12.723,-6.055 13.323,-6.055 13.923,-6.055 14.523,-6.055 9.123,-5.455 9.723,-5.455 10.323,-5.455 10.923,-5.455 11.523,-5.455 12.123,-5.455 12.723,-5.455 13.323,-5.455 13.923,-5.455 14.523,-5.455 10.323,-4.855 10.923,-4.855 11.523,-4.855 12.123,-4.855 12.723,-4.855 13.323,-4.855 13.923,-4.855 14.523,-4.855 10.323,-4.255 10.923,-4.255 11.523,-4.255 12.123,-4.255 12.723,-4.255 13.323,-4.255 13.923,-4.255 14.523,-4.255
  other v2: 23.352,-6.162 23.952,-6.162 24.552,-6.162 20.477,-6.077 23.352,-5.562 23.952,-5.562 24.552,-5.562 19.877,-5.477 20.477,-5.477
VMS: 
VOUT1: F2.2 pad.3@24.5,-7.769
  other v1: 9.321,-17.901 9.933,-17.891 22.059,-8.071 22.059,-7.521
  other v2: 23.352,-7.769 23.952,-7.769 24.552,-7.769
VXO: C34.2 R43.1 U5.1 | length 3.1
  Top Layer w0.5: R43.1 C34.2 16.683,-12.185 U5.1
XGND: 

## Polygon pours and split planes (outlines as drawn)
SGND on Bottom Layer "Bottom Layer-No Net" (solid, remove dead copper, pour order 67): 19.802,-6.974 18.749,-6.974 18.353,-7.37 18.353,-10.597 17.762,-11.188 11.437,-17.513 11.402,-17.513 5.915,-17.513 5.535,-17.893 5.535,-38.949 6.44,-39.853 6.992,-40.406 8.207,-40.406 21.45,-40.406 21.45,-11.29 21.477,-11.263 21.477,-7.368 21.206,-7.097 21.083,-6.974 20.636,-6.974
VIN on Bottom Layer "Bottom Layer-No Net" (solid, remove dead copper, pour order 62): 16.82,-15.131 17.987,-15.131 18.672,-14.445 18.368,-14.141 18.368,-13.926 18.368,-7.701 17.887,-7.221 17.624,-6.957 16.42,-6.957 15.696,-6.957 15.024,-6.286 cw(c15.609,-5.701) 14.782,-5.701 14.782,-5.43 14.782,-4.323 ccw(c14.429,-4.323) 14.429,-3.97 8.591,-3.97 ccw(c8.591,-4.378) 8.184,-4.378 8.184,-4.95 ccw(c8.688,-4.95) 8.331,-5.307 14.32,-11.296 cw(c14.175,-11.44) 14.38,-11.44 14.38,-14.473 ccw(c15.045,-14.473) 15.045,-15.138
SGND on Bottom Layer "Bottom Layer-No Net" (solid, remove dead copper, pour order 57): 7.298,-15.287 9.012,-13.573 9.012,-12.632 9.012,-10.28 9.183,-10.109 11.825,-10.109 12.147,-10.431 13.355,-11.639 13.355,-12.452 13.355,-13.675 13.025,-14.004 10.144,-16.885 8.047,-16.885 7.298,-16.136
VIN on Bottom Layer "Bottom Layer-No Net" (solid, remove dead copper, pour order 103): 15.072,-15.141 16.809,-15.141 17.48,-14.47 17.48,-8.002 16.42,-6.942 cw(c16.42,-5.32) 15.273,-6.467 15.2,-6.394 13.193,-4.386 ccw(c11.396,-6.182) 11.396,-3.642 9.82,-3.642 8.551,-3.642 ccw(c8.551,-4.006) 8.187,-4.006 8.187,-4.959 ccw(c8.679,-4.959) 8.331,-5.307 14.263,-11.239 cw(c13.535,-11.967) 14.565,-11.967 14.565,-14.641 ccw(c15.054,-14.641) 15.054,-15.131
SGND on Top Layer "Bottom Layer-No Net" (solid, remove dead copper, pour order 63): 21.593,-40.254 21.711,-40.137 21.711,-26.735 21.711,-21.301 22.912,-20.1 22.994,-20.018 22.994,-19.867 22.994,-19.539 22.92,-19.464 21.842,-19.464 21.193,-18.815 21.193,-17.909 20.494,-17.211 19.678,-16.395 13.218,-16.395 12.972,-16.395 11.68,-17.687 5.742,-17.687 5.535,-17.893 5.525,-17.904 5.525,-19.615 5.525,-38.775 6.761,-40.012 7.155,-40.406 8.207,-40.406 21.441,-40.406 21.584,-40.263
VDS on Top Layer "Bottom Layer-No Net" (solid, remove dead copper, pour order 58): 5.7,-14.457 7.187,-14.457 10.449,-11.196 11.509,-11.196 12.948,-11.196 13.194,-10.949 13.194,-8.803 13.037,-8.646 9.144,-8.646 8.974,-8.476 8.932,-8.435 8.932,-8.224 8.932,-8.03 8.78,-7.877 7.883,-7.877 7.481,-7.877 7.395,-7.962 7.263,-8.094 7.263,-8.613 7.263,-10.496 6.643,-11.117 6.633,-11.127 5.968,-11.127 5.379,-11.715 5.379,-14.137 5.7,-14.457
SGND on Signal Layer 1 "Bottom Layer-No Net" (solid, remove dead copper, pour order 66): 19.802,-6.974 18.749,-6.974 18.353,-7.37 18.353,-10.597 17.762,-11.188 11.437,-17.513 11.402,-17.513 5.915,-17.513 5.535,-17.893 5.535,-38.949 6.44,-39.853 6.992,-40.406 8.207,-40.406 21.45,-40.406 21.45,-11.29 21.477,-11.263 21.477,-7.368 21.206,-7.097 21.083,-6.974 20.636,-6.974
VIN on Signal Layer 1 "Bottom Layer-No Net" (solid, remove dead copper, pour order 61): 9.99,-3.958 10.001,-3.969 14.611,-3.969 14.785,-4.143 14.785,-5.9 ccw(c15.003,-5.9) 14.849,-6.054 15.267,-6.472 ccw(c16.42,-5.32) 16.42,-6.95 16.695,-7.225 cw(c15.726,-8.194) 17.097,-8.194 17.097,-10.599 cw(c16.482,-10.599) 16.482,-11.214 8.661,-11.214 8.201,-10.754 6.427,-10.754 5.276,-9.602 5.276,-5.785 5.378,-5.683 7.629,-5.683 7.997,-5.315 7.997,-3.868 8.414,-3.45 9.533,-3.45 9.725,-3.642
SGND on Signal Layer 2 "Bottom Layer-No Net" (solid, remove dead copper, pour order 65): 19.802,-6.974 18.749,-6.974 18.353,-7.37 18.353,-10.597 17.762,-11.188 11.437,-17.513 11.402,-17.513 5.915,-17.513 5.535,-17.893 5.535,-38.949 6.44,-39.853 6.992,-40.406 8.207,-40.406 21.45,-40.406 21.45,-11.29 21.477,-11.263 21.477,-7.368 21.206,-7.097 21.083,-6.974 20.636,-6.974
VIN on Signal Layer 2 "Bottom Layer-No Net" (solid, remove dead copper, pour order 60): 9.99,-3.958 10.08,-4.048 12.191,-4.048 14.536,-4.048 14.785,-4.297 14.785,-5.9 ccw(c15.003,-5.9) 14.849,-6.054 15.019,-6.224 15.267,-6.472 ccw(c16.42,-5.32) 16.42,-6.95 16.695,-7.225 cw(c15.726,-8.194) 17.097,-8.194 17.097,-10.599 cw(c16.482,-10.599) 16.482,-11.214 8.661,-11.214 8.324,-10.876 8.201,-10.754 6.778,-10.754 6.427,-10.754 5.276,-9.602 5.276,-5.785 5.378,-5.683 7.629,-5.683 7.882,-5.43 7.997,-5.315 7.997,-4.779 7.997,-3.868 8.414,-3.45 9.533,-3.45 9.725,-3.642
SGND on Signal Layer 2 "Bottom Layer-No Net" (solid, remove dead copper, pour order 59): 5.601,-5.303 7.432,-5.303 7.619,-5.116 7.619,-2.501 7.402,-2.285 7.329,-2.212 6.98,-2.212 6.553,-2.212 6.192,-2.572 5.538,-3.227 5.538,-5.139 5.538,-5.19 5.641,-5.294

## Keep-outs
Keep-Out Layer:
  circle w0.1: c10.909,-12.393 r0.67
  circle w0.1: c21.897,-33.799 r0.67
  circle w0.1: c10.897,-33.793 r0.67
  circle w0.1: c21.909,-12.399 r0.67
  lines w0.1: 5.228,-4.393 5.225,-9.653 6.724,-9.654 6.723,-10.754 5.225,-10.753 5.21,-37.409 ccw(c8.207,-37.409) 8.207,-40.406 25.296,-40.406 ; 5.232,-4.393 cw(c8.229,-4.393) 8.229,-1.396 25.304,-1.396 cw(c25.304,-4.393) 28.3,-4.393 ; 25.296,-40.404 ccw(c25.296,-37.407) 28.293,-37.407 28.302,-4.393 ; 25.45,-37.6 25.45,-32.4 26.55,-32.4 26.55,-37.6 25.45,-37.6 ; 25.45,-9.369 25.45,-2.669 26.55,-2.669 26.55,-9.369 25.45,-9.369

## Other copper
Top Layer:
  rectangle net SWRST: 14.733,-39.341 15.556,-38.865
  rectangle net VDD1: 18.702,-8.372 19.961,-7.694
  region net SWDIO1: 26.661,-8.065 28.158,-8.065 28.171,-8.078 28.171,-9.493 27.489,-10.175 26.051,-10.175 25.836,-9.96 25.902,-9.894 26.522,-9.894 26.661,-9.755
  region net 3.3V: 18.062,-16.407 19.216,-16.407 20.019,-17.211 20.494,-17.211 20.597,-17.314 20.597,-18.032 20.506,-18.123 19.049,-18.123 18.609,-18.564 18.609,-19.071 18.459,-19.221 17.992,-19.221 17.909,-19.138 17.909,-16.56
  region net V3V3: 21.447,-38.72 21.537,-38.81 21.537,-39.385 21.487,-39.435 17.769,-39.435 17.55,-39.216 17.55,-38.954 17.783,-38.72
  region net V3V3: 14.372,-38.39 15.758,-38.39 15.894,-38.254 15.894,-37.552 15.505,-37.162 15.505,-36.312 15.405,-36.312 14.251,-37.466 14.251,-38.269
  region net V3V3: 9.884,-31.486 9.884,-34.507 10.371,-34.994 10.371,-37.604 10.198,-37.777 9.144,-37.777 9.017,-37.649 9.017,-34.682 8.641,-34.306 8.641,-31.681 8.836,-31.486
  region net VOUT1: 25.383,-7.16 22.038,-7.16 21.797,-7.401 21.797,-8.215 21.953,-8.371 25.383,-8.371
  region net VIN: 25.4,-5.058 19.774,-5.058 19.476,-5.356 19.476,-6.353 19.688,-6.564 25.4,-6.564
  region net SGND: 25.384,-4.465 21.312,-4.465 21.046,-4.2 21.046,-2.647 22.066,-1.627 25.165,-1.627 25.39,-1.853 25.39,-4.459
  region net NetC101_2: 8.482,-25.399 9.4,-25.399 9.83,-24.969 9.83,-23.053 9.792,-23.015 8.645,-23.015 8.3,-23.359 8.3,-25.217
  region net NetC101_1: 5.689,-29.402 7.52,-29.402 7.724,-29.198 7.724,-23.195 7.539,-23.009 5.675,-23.009 5.473,-23.212 5.473,-29.186
  region net NetC10_2: 5.666,-5.882 6.684,-5.882 6.829,-6.026 6.829,-9.114 6.666,-9.277 5.718,-9.277 5.395,-8.954 5.395,-6.153
  region net NetC112_1: 8.799,-21.622 10.086,-21.622 10.281,-21.817 10.281,-22.243 10.419,-22.381 10.978,-22.381 11.086,-22.273 11.086,-19.857 10.978,-19.749 10.438,-19.749 10.342,-19.845 10.342,-20.907 10.134,-21.114 8.799,-21.114
  region net SGND: 8.047,-16.885 11.552,-16.885 13.478,-14.959 13.478,-13.592 13.086,-13.201 9.385,-13.201 7.298,-15.287 7.298,-16.136
  region net VIN: 16.945,-8.54 16.432,-8.54 16.017,-8.125 9.473,-8.125 cw(c9.473,-8.015) 9.363,-8.015 9.363,-7.921 ccw(c8.872,-7.921) 8.872,-7.429 8.208,-7.429 cw(c8.208,-7.193) 7.971,-7.193 7.971,-2.058 cw(c8.375,-2.058) 8.375,-1.654 19.878,-1.654 cw(c19.878,-2.381) 20.606,-2.381 20.606,-4.373 21.672,-5.439 21.914,-5.439 21.914,-6.43 21.78,-6.564 18.863,-6.564 18.46,-6.161 18.131,-5.194 18.131,-4.596 17.301,-3.766 15.297,-3.766 14.688,-3.157 9.798,-3.157 9.574,-3.381 9.574,-3.81 9.677,-3.913 9.801,-3.789 9.801,-3.487 9.913,-3.374 14.573,-3.374 14.816,-3.618 14.816,-5.931 15.019,-6.133 15.019,-7.357 15.354,-7.022 16.492,-7.022 17.041,-7.57 17.041,-8.444
  region net NetKEY1_1: 16.195,-4.148 17.058,-4.148 17.528,-4.618 18.115,-6.523 16.443,-6.387 16.321,-6.387 cw(c16.321,-5.437) 15.372,-5.437 15.372,-4.963 cw(c16.187,-4.963) 16.187,-4.147
  region net LEDA: 14.618,-22.443 14.954,-22.443 cw(c14.954,-22.614) 15.125,-22.614 15.125,-25.922 cw(c14.993,-25.922) 14.993,-26.054 14.817,-26.054 cw(c14.817,-25.879) 14.642,-25.879 14.642,-24.231 ccw(c14.103,-24.231) 14.484,-23.849 14.45,-23.815 cw(c14.99,-23.275) 14.227,-23.275 14.227,-22.632 cw(c14.414,-22.632) 14.414,-22.444
  region net NetQ1_3: 12.871,-23.444 13.397,-23.444 ccw(c13.397,-23.283) 13.558,-23.283 13.558,-22.514 cw(c14.338,-22.514) 14.338,-21.733 14.41,-21.733 ccw(c14.41,-21.446) 14.697,-21.446 14.697,-20.976 ccw(c14.293,-20.976) 14.293,-20.573 13.234,-20.573 ccw(c13.234,-21.115) 12.693,-21.115 12.693,-23.282 ccw(c12.852,-23.282) 12.852,-23.441
  region net PA9: 14.494,-17.681 15.479,-17.681 cw(c15.479,-17.891) 15.689,-17.891 15.689,-19.519 cw(c15.451,-19.519) 15.451,-19.757 14.582,-19.757 cw(c14.582,-19.424) 14.25,-19.424 14.25,-17.865 cw(c14.434,-17.865) 14.434,-17.681
  region net V3V3: 8.148,-26.425 8.148,-26.308 cw(c8.582,-26.308) 8.582,-25.873 9.51,-25.873 cw(c9.51,-26.624) 10.261,-26.624 10.261,-28.562 cw(c8.799,-28.562) 9.833,-29.596 9.316,-30.113 ccw(c9.529,-30.326) 9.227,-30.326 9.232,-30.326 9.298,-30.392 ccw(c9.339,-30.35) 9.339,-30.409 ccw(c9.339,-30.261) 9.444,-30.365 10.083,-29.727 ccw(c9.011,-28.655) 10.526,-28.655 10.526,-25.423 cw(c13.041,-25.423) 11.263,-23.644 11.349,-23.558 ccw(c10.931,-23.141) 11.522,-23.141 11.522,-18.154 cw(c12.29,-18.154) 11.747,-17.611 12.761,-16.597 cw(c13.218,-17.053) 13.218,-16.408 16.897,-16.408 cw(c16.897,-16.988) 17.478,-16.988 17.478,-19.081 cw(c17.339,-19.081) 17.339,-19.219 16.509,-19.219 cw(c16.509,-18.771) 16.061,-18.771 16.061,-17.913 ccw(c15.468,-17.913) 15.468,-17.321 14.289,-17.321 ccw(c14.289,-17.769) 13.841,-17.769 13.841,-19.767 cw(c13.586,-19.767) 13.586,-20.022 13.162,-20.022 ccw(c13.162,-20.976) 12.207,-20.976 12.207,-23.465 cw(c10.917,-23.465) 11.83,-24.377 ccw(c12.98,-25.528) 11.353,-25.528 11.353,-28.821 cw(c8.813,-28.821) 10.609,-30.617 10.299,-30.927 ccw(c11.975,-32.604) 9.604,-32.604 9.604,-34.2 cw(c9.42,-34.2) 9.42,-34.384 7.937,-34.384 cw(c7.937,-34.016) 7.568,-34.016 7.568,-33.221 cw(c7.88,-33.221) 7.659,-33 7.933,-32.727 ccw(c7.383,-32.178) 8.16,-32.178 8.16,-26.454 ccw(c8.118,-26.454)
  region net VDD: 16.752,-22.097 17.92,-22.097 ccw(c17.92,-21.97) 18.048,-21.97 18.048,-21.161 ccw(c17.8,-21.161) 17.8,-20.914 16.749,-20.914 ccw(c16.749,-21.12) 16.542,-21.12 16.542,-21.963 ccw(c16.677,-21.963) 16.677,-22.097
  region net SCL1: 17.369,-25.942 17.369,-22.673 cw(c17.509,-22.673) 17.509,-22.533 18.833,-22.533 cw(c18.833,-22.671) 18.972,-22.671 18.972,-23.172 cw(c18.798,-23.172) 18.798,-23.345 17.922,-23.345 ccw(c17.922,-23.648) 17.619,-23.648 17.619,-25.92 cw(c17.486,-25.92) 17.486,-26.053 17.477,-26.053 cw(c17.477,-25.946) 17.37,-25.946
  region net SDA1: 15.739,-22.54 16.981,-22.54 cw(c16.981,-22.679) 17.119,-22.679 17.119,-25.933 cw(c17.007,-25.933) 17.007,-26.045 16.978,-26.045 cw(c16.978,-25.935) 16.868,-25.935 16.868,-23.555 ccw(c16.614,-23.555) 16.614,-23.301 15.839,-23.301 cw(c15.839,-23.062) 15.601,-23.062 15.601,-22.665 cw(c15.724,-22.665) 15.724,-22.541
  region net SGND: 5.784,-29.826 7.442,-29.826 cw(c7.442,-30.068) 7.684,-30.068 7.684,-32.227 cw(c7.417,-32.227) 7.417,-32.494 7.033,-32.494 cw(c7.033,-32.259) 6.797,-32.259 6.797,-32.238 ccw(c6.239,-32.238) 6.239,-31.68 5.781,-31.68 cw(c5.781,-31.49) 5.591,-31.49 5.591,-30.001 cw(c5.762,-30.001) 5.762,-29.83
  region net VDD: 5.915,-32.054 6.185,-32.054 cw(c6.185,-32.249) 6.38,-32.249 6.38,-32.351 ccw(c6.739,-32.351) 6.485,-32.605 6.735,-32.855 cw(c6.385,-33.205) 6.88,-33.205 6.88,-35 cw(c6.605,-35) 6.605,-35.275 5.76,-35.275 cw(c5.76,-35.1) 5.585,-35.1 5.585,-32.229 cw(c5.758,-32.229) 5.758,-32.055
  region net NetC24_1: 6.621,-17.731 5.786,-17.731 ccw(c5.786,-17.997) 5.52,-17.997 5.52,-22.283 ccw(c5.858,-22.283) 5.858,-22.621 7.255,-22.621 ccw(c7.255,-22.529) 7.347,-22.529 7.347,-17.982 ccw(c7.098,-17.982) 7.098,-17.733
  region net VOUT1: 8.152,-17.513 ccw(c8.152,-17.734) 7.93,-17.734 7.93,-18.521 ccw(c8.182,-18.521) 8.182,-18.773 9.952,-18.773 ccw(c9.952,-18.528) 10.197,-18.528 10.197,-17.814 ccw(c9.896,-17.814) 9.896,-17.513
  region net SGND: 7.428,-5.303 ccw(c7.428,-5.116) 7.615,-5.116 7.615,-2.683 ccw(c7.136,-2.683) 7.136,-2.204 ccw(c7.136,-3.799) 5.541,-3.799 5.541,-5.139 ccw(c5.706,-5.139) 5.706,-5.303
Signal Layer 1:
  region net SGND: 23.181,-4.459 22.504,-5.136 22.504,-6.433 21.477,-7.46 21.477,-11.263 20.893,-11.847 20.893,-14.558 19.444,-14.558 19.444,-7.333 19.802,-6.974 20.636,-6.974 21.644,-5.966 21.644,-2.05 22.066,-1.627 25.165,-1.627 25.39,-1.853 25.39,-4.459
  region net VIN: 25.4,-5.058 23.397,-5.058 23.028,-5.428 23.028,-6.278 23.314,-6.564 25.4,-6.564
  region net VIN: 19.796,-1.654 20.868,-2.726 20.868,-6.295 20.63,-6.532 19.656,-6.532 18.131,-5.007 18.131,-4.596 16.126,-2.59 16.126,-1.928 16.4,-1.654
  region net VIN: 9.566,-5.175 8.393,-5.175 7.997,-4.779 7.997,-2.032 8.375,-1.654 18.405,-1.654 18.405,-3.766 10.182,-3.766 9.798,-4.15 9.798,-4.943
  region net SGND: 8.047,-16.885 11.552,-16.885 13.478,-14.959 13.478,-13.592 13.086,-13.201 9.385,-13.201 7.298,-15.287 7.298,-16.136
  region net SGND: 5.601,-5.303 6.998,-5.303 7.385,-4.916 7.385,-2.453 7.136,-2.204 6.49,-2.204 5.478,-3.217 5.478,-5.18
  region net VDS: 7.187,-14.457 9.012,-12.632 9.012,-12.127 8.012,-11.127 5.968,-11.127 5.379,-11.715 5.379,-14.137 5.7,-14.457
Signal Layer 2:
  rectangle net SGND: 22.824,-4.456 24.983,-2.474
  region net V3V3: 9.934,-36.653 10.313,-36.653 10.755,-37.094 15.557,-37.094 15.716,-37.254 15.716,-37.493 17.026,-38.803 18.965,-38.803 19.133,-38.971 19.133,-39.192 18.983,-39.342 16.858,-39.342 15.214,-37.698 9.961,-37.698 9.83,-37.567 9.83,-36.756
  region net SGND: 8.047,-16.885 11.552,-16.885 13.478,-14.959 13.478,-13.592 13.086,-13.201 9.385,-13.201 7.298,-15.287 7.298,-16.136
  region net VIN: 9.566,-5.175 8.393,-5.175 7.997,-4.779 7.997,-2.032 8.375,-1.654 21.116,-1.654 21.905,-2.443 21.905,-4.354 22.61,-5.058 25.4,-5.058 25.4,-6.564 25.393,-6.572 19.508,-6.572 18.131,-5.194 18.131,-4.596 17.301,-3.766 10.182,-3.766 9.798,-4.15 9.798,-4.943
  region net VDS: 7.187,-14.457 9.012,-12.632 9.012,-12.127 8.012,-11.127 5.968,-11.127 5.379,-11.715 5.379,-14.137 5.7,-14.457
Bottom Layer:
  rectangle net SWCLK1: 26.852,-7.243 28.043,-6.691
  rectangle net SDA: 26.852,-5.643 28.043,-5.091
  rectangle net SCL: 26.852,-4.043 28.043,-3.491
  region net VOUT1: 25.383,-7.16 25.383,-8.371 25.383,-8.372 19.961,-8.372 19.961,-7.358 20.159,-7.16
  region net SGND: 12.281,-33.493 13.397,-33.493 13.545,-33.641 14.14,-33.641 14.305,-33.806 14.305,-34.493 14.03,-34.767 13.587,-34.767 13.224,-34.404 12.341,-34.404 12.146,-34.21 12.146,-33.628
  region net VOUT1: 19.813,-7.16 19.444,-7.529 19.444,-14.042 17.988,-15.497 13.418,-15.497 11.402,-17.513 8.822,-17.513 8.558,-17.777 8.558,-18.165 8.792,-18.399 11.691,-18.399 13.778,-16.312 18.507,-16.312 20.111,-14.709 20.111,-8.581 20.321,-8.371 22.152,-8.371 22.379,-8.144 22.379,-7.306 22.233,-7.16
  region net VIN: 25.4,-5.058 19.774,-5.058 19.476,-5.356 19.476,-6.353 19.688,-6.564 25.4,-6.564
  region net VIN: 14.429,-3.97 14.77,-4.311 14.77,-5.975 15.267,-6.472 15.267,-7.406 14.826,-7.847 13.159,-7.847 11.871,-6.558 11.871,-4.271 12.172,-3.97
  region net VDS: 5.7,-14.457 7.187,-14.457 8.553,-13.092 8.553,-11.676 7.994,-11.117 5.978,-11.117 5.387,-11.708 5.387,-14.145
  pour cut-out: 13.265,-29.483 13.587,-29.805 13.587,-36.76 13.098,-37.248 12.168,-37.248 11.703,-36.783 11.703,-29.904 12.124,-29.483
  region net SGND: 25.384,-4.465 18.001,-4.465 17.301,-3.766 10.137,-3.766 9.804,-3.433 8.102,-3.433 7.615,-3.92 7.615,-5.116 13.899,-11.4 13.899,-14.538 11.552,-16.885 8.047,-16.885 7.298,-16.136 7.298,-15.287 9.385,-13.201 12.096,-13.201 12.339,-12.957 12.339,-12.121 11.763,-11.544 9.01,-11.544 5.539,-8.074 5.539,-3.883 cw(c7.106,-3.883) 5.998,-2.775 6.395,-2.378 cw(c8.191,-4.174) 8.191,-1.634 25.038,-1.634 cw(c25.038,-1.98) 25.383,-1.98

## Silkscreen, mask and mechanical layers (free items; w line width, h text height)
Top Overlay:
  circle w0.05: c16.412,-5.352 r1.591
  circle w0.1: c16.412,-5.352 r0.9
  lines w0.1: 8.854,-4.912 cw(c8.855,-4.537) 8.855,-4.162 ; 10.297,-34.091 10.296,-35.294 11.496,-35.295 11.497,-34.091 ; 10.297,-33.494 10.298,-32.294 11.498,-32.295 11.497,-33.495 ; 10.308,-12.691 10.308,-13.894 11.508,-13.895 11.508,-12.691 ; 10.309,-12.094 10.309,-10.894 11.509,-10.895 11.509,-12.095 ; 12.545,-25.196 12.545,-30.396 20.945,-30.396 20.945,-25.196 ; 13.745,-30.396 13.745,-29.596 19.745,-29.596 19.745,-30.396 ; 21.297,-34.097 21.296,-35.3 22.496,-35.301 22.497,-34.097 ; 21.297,-33.5 21.298,-32.3 22.498,-32.301 22.497,-33.501 ; 21.308,-12.697 21.308,-13.9 22.508,-13.901 22.508,-12.697 ; 21.309,-12.1 21.309,-10.9 22.509,-10.901 22.509,-12.101 ; 25.162,-6.603 7.662,-6.594 ccw(c7.661,-7.494) 6.761,-7.493 6.744,-38.693 ccw(c7.644,-38.694) 7.644,-39.594 25.144,-39.603 ccw(c25.144,-38.703) 26.044,-38.704 26.045,-37.556 ; 26.048,-32.256 26.06,-9.39 ; 6.604,-4.91 cw(c6.605,-4.535) 6.605,-4.16 6.855,-4.161 cw(c6.855,-4.536) 6.854,-4.911 6.604,-4.91
Bottom Overlay:
  lines w0.1: 6.723,-10.714 28.3,-10.714 28.3,-9.714 6.724,-9.714 ; 21.45,-40.406 21.45,-1.434 ; 25.5,-40.406 25.5,-1.434 ; 26.5,-40.406 26.5,-1.434
  text "VCC" at 10.913,-29.935 h0.6
  text "SWDIO" at 13.412,-31.696 h0.6
  text "SWCLK" at 10.057,-32.725 h0.6
  text "GND" at 13.367,-34.142 h0.6
  text "B00T0" at 10.443,-35.502 h0.6
  text "SWRST" at 13.383,-36.66 h0.6
Top Solder:
  rectangle: 9.02,-2.935 19.94,-1.786
  rectangle: 9.435,-8.091 14.736,-3.538
Bottom Solder:
  rectangle: 10.645,-3.438 20.791,-1.814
